// Mitsubishi GX Works2 project: MODBUS主从   PLC: FX3U/FX3UC

PROGRAM MAIN
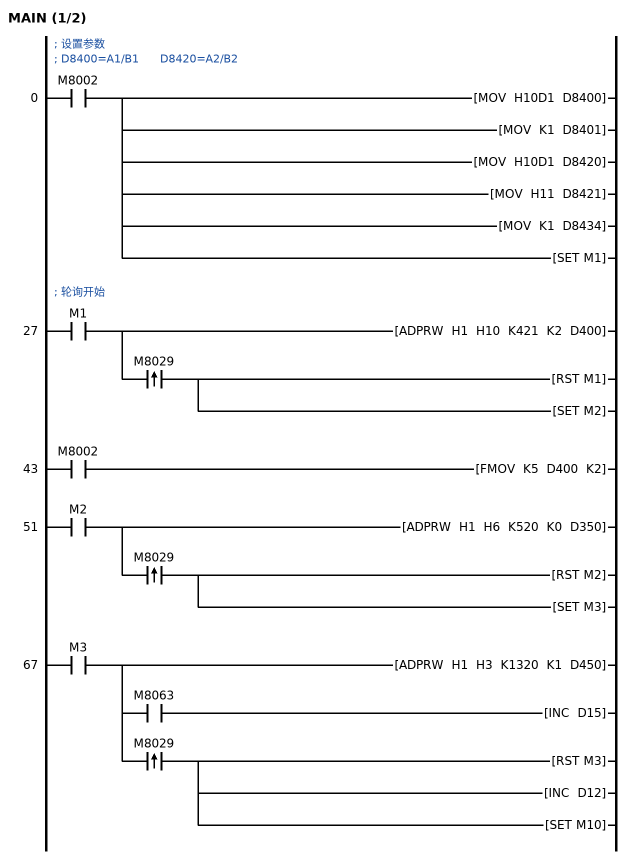
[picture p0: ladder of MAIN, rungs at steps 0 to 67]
; 设置参数
; D8400=A1/B1      D8420=A2/B2
0     LD      M8002
      MOV     H10D1 D8400
        [note] 485,115200,1停止,无校验位,8
      MOV     K1 D8401
        [note] MODBUS主站,RTU
      MOV     H10D1 D8420
        [note] 485,115200,1停止,无校验位,8
      MOV     H11 D8421
        [note] MODBUS从站,RTU
      MOV     K1 D8434
        [note] 从站地址1
      SET     M1
; 轮询开始
27    LD      M1
      ADPRW   H1 H10 K421 K2 D400
        [note] H10写入多个,D400写入寄存器421
      ANDP    M8029
      RST     M1
        [note] D401写入寄存器422
      SET     M2
43    LD      M8002
      FMOV    K5 D400 K2
        [note] 初始D400/401赋初值
51    LD      M2
      ADPRW   H1 H6 K520 K0 D350
        [note] H6,写入单个寄存器
      ANDP    M8029
      RST     M2
      SET     M3
67    LD      M3
      ADPRW   H1 H3 K1320 K1 D450
        [note] H3,读取单个寄存器
      MPS
      AND     M8063
      INC     D15
        [note] 通信错误次数
      MPP
      ANDP    M8029
      RST     M3
      INC     D12
        [note] 轮询次数
      SET     M10
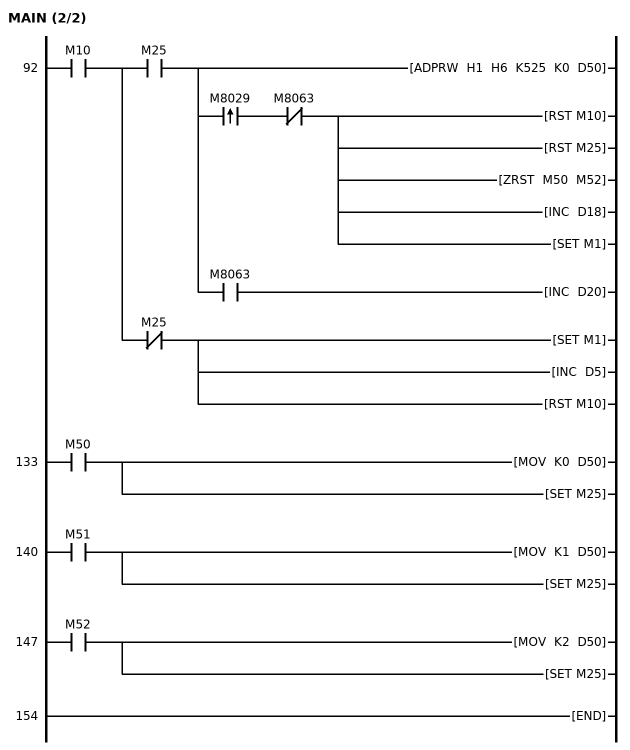
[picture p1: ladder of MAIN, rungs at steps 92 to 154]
92    LD      M10
      MPS
      AND     M25
      ADPRW   H1 H6 K525 K0 D50
        [note] 触点控制
      MPS
      ANDP    M8029
      ANI     M8063
      RST     M10
      RST     M25
      ZRST    M50 M52
      INC     D18
        [note] 接收次数
      SET     M1
      MPP
      AND     M8063
      INC     D20
      MPP
      ANI     M25
      SET     M1
        [note] 未触发的时候跳过
      INC     D5
        [note] 错误次数
      RST     M10
133   LD      M50
      MOV     K0 D50
        [note] 按钮触发
      SET     M25
140   LD      M51
      MOV     K1 D50
      SET     M25
147   LD      M52
      MOV     K2 D50
      SET     M25
154   END
END_PROGRAM
